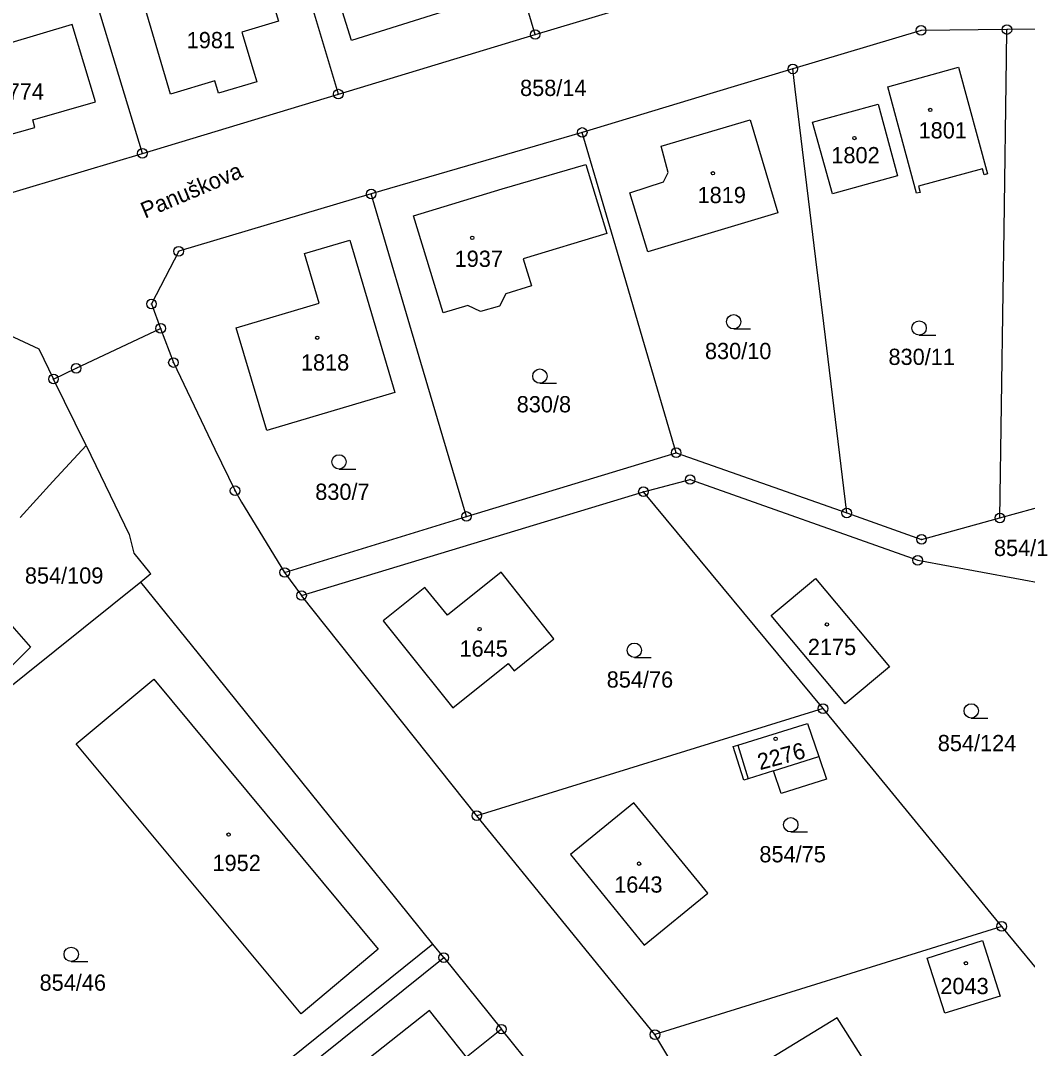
# Model space of a CAD drawing. Extents: x -680203 to -673936, y -1102717 to -1093650.
# Drawn here: x -679106 to -679000.6, y -1097626.7 to -1097519.2 of the extents above; entities that cross this region are included whole.
import ezdxf

# ---------------------------------------------------------------- set-up
doc = ezdxf.new("R2010")
doc.units = 0
for name, color, linetype in [('SOxx02xx_Koleje_param další_Popis10', 7, 'Continuous'), ('SOxx02xx_Staničení_Popis10', 7, 'Continuous'), ('SOxxxxxx_Koleje_hlavní_body_Popis10', 7, 'Continuous'), ('SOxxxxxx_Koleje_param další_Popis10', 7, 'Continuous'), ('SOxxxxxx_Osa_bod_P', 7, 'Continuous'), ('SOxxxxxx_Staničení_Popis10', 7, 'Continuous'), ('x_prac', 7, 'Continuous')]:
    doc.layers.add(name, color=color, linetype=linetype)

msp = doc.modelspace()

# ---------------------------------------------------------------- linework, layer by layer
at = {"layer": 'SOxx02xx_Koleje_param další_Popis10'}
for centre, radius in [((-679052.09, -1097520.62), 0.5), ((-679011.7, -1097520.18), 0.5), ((-679011.7, -1097520.18), 0.0303), ((-679002.71, -1097520.1), 0.5), ((-679002.71, -1097520.1), 0.0303), ((-679052.09, -1097520.62), 0.0303), ((-679025.12, -1097524.22), 0.5), ((-679025.12, -1097524.22), 0.0303), ((-679072.69, -1097526.85), 0.5), ((-679072.69, -1097526.85), 0.0303), ((-679047.16, -1097530.86), 0.5), ((-679047.16, -1097530.86), 0.0303), ((-679093.2, -1097533.05), 0.5), ((-679093.2, -1097533.05), 0.0303), ((-679069.25, -1097537.3), 0.5), ((-679069.25, -1097537.3), 0.0303), ((-679089.4, -1097543.3), 0.5), ((-679089.4, -1097543.3), 0.0303), ((-679092.25, -1097548.81), 0.5), ((-679092.25, -1097548.81), 0.0303), ((-679091.29, -1097551.36), 0.5), ((-679091.29, -1097551.36), 0.0303), ((-679089.95, -1097554.94), 0.5), ((-679100.13, -1097555.54), 0.5), ((-679100.13, -1097555.54), 0.0303), ((-679089.95, -1097554.94), 0.0303), ((-679102.5, -1097556.66), 0.5), ((-679102.5, -1097556.66), 0.0303), ((-679037.33, -1097564.37), 0.5), ((-679037.33, -1097564.37), 0.0303), ((-679035.87, -1097567.18), 0.5), ((-679035.87, -1097567.18), 0.0303), ((-679083.5, -1097568.35), 0.5), ((-679083.5, -1097568.35), 0.0303), ((-679040.76, -1097568.45), 0.5), ((-679040.76, -1097568.45), 0.0303), ((-679059.28, -1097571.04), 0.5), ((-679019.48, -1097570.68), 0.5), ((-679019.48, -1097570.68), 0.0303), ((-679003.45, -1097571.2), 0.5), ((-679059.28, -1097571.04), 0.0303), ((-679003.45, -1097571.2), 0.0303), ((-679011.65, -1097573.44), 0.5), ((-679011.65, -1097573.44), 0.0303), ((-679012.05, -1097575.63), 0.5), ((-679012.05, -1097575.63), 0.0303), ((-679078.31, -1097576.9), 0.5), ((-679078.31, -1097576.9), 0.0303), ((-679076.54, -1097579.31), 0.5), ((-679076.54, -1097579.31), 0.0303), ((-679021.96, -1097591.15), 0.5), ((-679021.96, -1097591.15), 0.0303), ((-679058.2, -1097602.35), 0.5), ((-679058.2, -1097602.35), 0.0303), ((-679003.26, -1097613.93), 0.5), ((-679003.26, -1097613.93), 0.0303), ((-679061.66, -1097617.2), 0.5), ((-679061.66, -1097617.2), 0.0303), ((-679055.62, -1097624.69), 0.5), ((-679055.62, -1097624.69), 0.0303), ((-679039.55, -1097625.26), 0.5), ((-679039.55, -1097625.26), 0.0303)]:
    msp.add_circle(centre, radius, dxfattribs=at)
at = {"layer": 'SOxxxxxx_Koleje_hlavní_body_Popis10'}
for p, q in [((-679031.31, -1097551.42), (-679029.56, -1097551.42)), ((-679011.9, -1097552.08), (-679010.15, -1097552.08)), ((-679051.6, -1097557.11), (-679049.85, -1097557.11)), ((-679072.62, -1097566.08), (-679070.87, -1097566.08)), ((-679041.71, -1097585.79), (-679039.96, -1097585.79)), ((-679006.45, -1097592.13), (-679004.7, -1097592.13)), ((-679025.34, -1097604.05), (-679023.59, -1097604.05)), ((-679100.65, -1097617.6), (-679098.9, -1097617.6))]:
    msp.add_line(p, q, dxfattribs=at)
for centre in [(-679031.31, -1097550.67), (-679011.9, -1097551.33), (-679051.6, -1097556.36), (-679072.62, -1097565.33), (-679041.71, -1097585.04), (-679006.45, -1097591.38), (-679025.34, -1097603.3), (-679100.65, -1097616.85)]:
    msp.add_circle(centre, 0.75, dxfattribs=at)
at = {"layer": 'SOxxxxxx_Koleje_param další_Popis10'}
for centre in [(-679010.74, -1097528.51), (-679018.67, -1097531.45), (-679033.48, -1097535.14), (-679058.67, -1097541.89), (-679074.9, -1097552.35), (-679021.56, -1097582.33), (-679057.9, -1097582.83), (-679026.92, -1097594.31), (-679084.18, -1097604.33), (-679041.21, -1097607.37), (-679007.01, -1097617.79)]:
    msp.add_circle(centre, 0.175, dxfattribs=at)
at = {"layer": 'SOxxxxxx_Staničení_Popis10'}
for p, q in [((-679030.88, -1097594.96), (-679029.78, -1097598.49)), ((-679027.14, -1097597.65), (-679022.41, -1097596.15))]:
    msp.add_line(p, q, dxfattribs=at)
at = {"layer": 'x_prac'}
for p, q in [((-679052.09, -1097520.62), (-679064.54, -1097478.98)), ((-679072.69, -1097526.85), (-679085.11, -1097485.36)), ((-679093.2, -1097533.05), (-679105.63, -1097491.91)), ((-679052.09, -1097520.62), (-679031.47, -1097514.43)), ((-679072.69, -1097526.85), (-679052.09, -1097520.62)), ((-679093.2, -1097533.05), (-679072.69, -1097526.85)), ((-679047.16, -1097530.86), (-679069.25, -1097537.3)), ((-679115.21, -1097539.66), (-679093.2, -1097533.05)), ((-679100.13, -1097555.54), (-679091.29, -1097551.36)), ((-679102.5, -1097556.66), (-679100.13, -1097555.54)), ((-679099.1, -1097563.62), (-679102.5, -1097556.66)), ((-679102.59, -1097567.38), (-679099.1, -1097563.62)), ((-679059.28, -1097571.04), (-679037.33, -1097564.37)), ((-679037.33, -1097564.37), (-679019.48, -1097570.68)), ((-679105.99, -1097571.15), (-679102.59, -1097567.38)), ((-679040.76, -1097568.45), (-679035.87, -1097567.18)), ((-679003.45, -1097571.2), (-678987, -1097566.67)), ((-679076.54, -1097579.31), (-679040.76, -1097568.45)), ((-679021.96, -1097591.15), (-679040.76, -1097568.45)), ((-679078.31, -1097576.9), (-679059.28, -1097571.04)), ((-679078.31, -1097576.9), (-679076.54, -1097579.31)), ((-679093.36, -1097577.91), (-679108.85, -1097590.31)), ((-679058.2, -1097602.35), (-679076.54, -1097579.31)), ((-679021.96, -1097591.15), (-679058.2, -1097602.35)), ((-679003.26, -1097613.93), (-679021.96, -1097591.15)), ((-679039.55, -1097625.26), (-679058.2, -1097602.35)), ((-679003.26, -1097613.93), (-679039.55, -1097625.26)), ((-678984.53, -1097636.69), (-679003.26, -1097613.93)), ((-679062.79, -1097615.8), (-679102.21, -1097647.44)), ((-679061.66, -1097617.2), (-679062.79, -1097615.8)), ((-679101.21, -1097648.88), (-679061.66, -1097617.2)), ((-679061.66, -1097617.2), (-679055.62, -1097624.69)), ((-679055.62, -1097624.69), (-679059.29, -1097627.63)), ((-679051.84, -1097629.37), (-679055.62, -1097624.69))]:
    msp.add_line(p, q, dxfattribs=at)
for points in [[(-679064.7, -1097506.92), (-679062.26, -1097506.15), (-679060.95, -1097510.34), (-679063.38, -1097511.1), (-679061.19, -1097518.07), (-679071.31, -1097521.25), (-679075.76, -1097507.08), (-679065.65, -1097503.9), (-679064.7, -1097506.92)], [(-679085.23, -1097526.75), (-679085.63, -1097525.48), (-679090.25, -1097526.85), (-679093.08, -1097517.28), (-679084.82, -1097514.82), (-679085.1, -1097513.86), (-679080.94, -1097512.61), (-679078.94, -1097519.22), (-679082.78, -1097520.37), (-679081.61, -1097524.3), (-679081.23, -1097525.58), (-679085.23, -1097526.75)], [(-679111.14, -1097532.23), (-679104.45, -1097530.33), (-679104.68, -1097529.54), (-679098.09, -1097527.67), (-679100.56, -1097519.58), (-679113.77, -1097523.5), (-679112.88, -1097526.46), (-679114.14, -1097528.41), (-679112.01, -1097529.36), (-679111.14, -1097532.23)], [(-679002.71, -1097520.1), (-679011.7, -1097520.18), (-679025.12, -1097524.22)], [(-679003.45, -1097571.2), (-679003.1, -1097547.62), (-679003.01, -1097541.04), (-679002.75, -1097523.12), (-679002.71, -1097520.1)], [(-678979.71, -1097520.32), (-678988.1, -1097520), (-678988.8, -1097519.98), (-679002.71, -1097520.1)], [(-679025.12, -1097524.22), (-679033.46, -1097526.73), (-679047.16, -1097530.86)], [(-679019.48, -1097570.68), (-679022.02, -1097549.7), (-679022.56, -1097545.28), (-679024.86, -1097526.35), (-679025.12, -1097524.22)], [(-679004.74, -1097535.2), (-679005.11, -1097535.3), (-679005.28, -1097534.66), (-679011.96, -1097536.47), (-679011.78, -1097537.13), (-679012.16, -1097537.23), (-679015.18, -1097526.08), (-679007.77, -1097524.02), (-679004.74, -1097535.2)], [(-679023.06, -1097529.78), (-679019.49, -1097528.81), (-679016.2, -1097527.91), (-679014.16, -1097535.39), (-679017.43, -1097536.3), (-679020.98, -1097537.28), (-679023.06, -1097529.78)], [(-679038.89, -1097532.3), (-679029.57, -1097529.55), (-679026.7, -1097539.28), (-679040.3, -1097543.34), (-679042.17, -1097537.18), (-679038.65, -1097536.03), (-679038.16, -1097535.05), (-679038.89, -1097532.3)], [(-679037.33, -1097564.37), (-679040.64, -1097553.09), (-679042.78, -1097545.8), (-679047.16, -1097530.86)], [(-679059.12, -1097548.96), (-679061.73, -1097549.73), (-679064.82, -1097539.58), (-679055.55, -1097536.76), (-679046.77, -1097534.23), (-679044.59, -1097541.42), (-679053.33, -1097544.07), (-679052.47, -1097546.9), (-679055.15, -1097547.75), (-679055.81, -1097549.04), (-679057.82, -1097549.61), (-679059.12, -1097548.96)], [(-679069.25, -1097537.3), (-679089.4, -1097543.3), (-679092.25, -1097548.81), (-679091.29, -1097551.36)], [(-679059.28, -1097571.04), (-679061.75, -1097562.7), (-679064.05, -1097554.92), (-679069.25, -1097537.3)], [(-679071.5, -1097542.12), (-679066.77, -1097558.08), (-679080.16, -1097562.04), (-679083.37, -1097551.31), (-679074.68, -1097548.71), (-679076.22, -1097543.53), (-679071.5, -1097542.12)], [(-679132.38, -1097556.26), (-679111.48, -1097550.04), (-679104.04, -1097553.49), (-679102.5, -1097556.66)], [(-679091.29, -1097551.36), (-679089.95, -1097554.94), (-679085.63, -1097563.99), (-679083.5, -1097568.35), (-679082.82, -1097569.54), (-679078.31, -1097576.9)], [(-679099.1, -1097563.62), (-679094.59, -1097572.94), (-679094.09, -1097574.9)], [(-679035.87, -1097567.18), (-679012.05, -1097575.63), (-678998.49, -1097578.13)], [(-679019.48, -1097570.68), (-679011.65, -1097573.44), (-679003.45, -1097571.2)], [(-679094.09, -1097574.9), (-679092.45, -1097576.92), (-679092.33, -1097577.06), (-679093.36, -1097577.91)], [(-679111.55, -1097577.18), (-679104.92, -1097584.73), (-679109.47, -1097589.28), (-679115.94, -1097581.98)], [(-679063.63, -1097578.46), (-679068, -1097581.97), (-679065.64, -1097584.92), (-679060.71, -1097591.08), (-679054.91, -1097586.41), (-679054.28, -1097587.19), (-679050.14, -1097583.85), (-679055.64, -1097576.86), (-679061.25, -1097581.38), (-679063.63, -1097578.46)], [(-679062.79, -1097615.8), (-679067.7, -1097609.72), (-679072.6, -1097603.64), (-679077.51, -1097597.56), (-679082.42, -1097591.48), (-679087.32, -1097585.39), (-679093.36, -1097577.91)], [(-679014.99, -1097586.76), (-679019.65, -1097590.63), (-679027.4, -1097581.4), (-679022.74, -1097577.53), (-679014.99, -1097586.76)], [(-679100.12, -1097594.84), (-679092.01, -1097588.08), (-679068.51, -1097616.31), (-679076.59, -1097623.09), (-679100.12, -1097594.84)], [(-679030.88, -1097594.96), (-679023.57, -1097592.7), (-679022.41, -1097596.15), (-679021.61, -1097598.52), (-679026.34, -1097600.04), (-679027.14, -1097597.65), (-679029.78, -1097598.49), (-679030.26, -1097598.64), (-679031.36, -1097595.11), (-679030.88, -1097594.96)], [(-679041.76, -1097601.02), (-679048.39, -1097606.41), (-679040.69, -1097615.89), (-679034.03, -1097610.47), (-679041.76, -1097601.02)], [(-679011.05, -1097617.27), (-679005.26, -1097615.42), (-679003.43, -1097621.24), (-679009.21, -1097623.02), (-679011.05, -1097617.27)], [(-679059.29, -1097627.63), (-679063.15, -1097622.73), (-679071.19, -1097629.09), (-679073.32, -1097630.76), (-679069.96, -1097635), (-679067.84, -1097633.33), (-679067.28, -1097634.04)], [(-679014.94, -1097632.24), (-679020.47, -1097623.5), (-679031.15, -1097630.03), (-679028.69, -1097633.9), (-679028.18, -1097633.58), (-679024.97, -1097638.57), (-679014.94, -1097632.24)], [(-679025.48, -1097651.06), (-679031.92, -1097637.99), (-679039.55, -1097625.26)]]:
    msp.add_lwpolyline(points, dxfattribs=at)

# ---------------------------------------------------------------- texts
at = {"layer": 'SOxx02xx_Staničení_Popis10'}
msp.add_text('Panuškova', height=1.7, rotation=23, dxfattribs=at).set_placement((-679092.92, -1097539.9))
at = {"layer": 'SOxxxxxx_Osa_bod_P'}
for s, p in [('1981', (-679088.56, -1097522.05)), ('858/14', (-679053.67, -1097527.05)), ('1774', (-679108.56, -1097527.42)), ('1801', (-679011.96, -1097531.49)), ('1802', (-679021.09, -1097534.09)), ('1819', (-679035.09, -1097538.26)), ('1937', (-679060.52, -1097544.93)), ('830/10', (-679034.32, -1097554.58)), ('830/11', (-679015.11, -1097555.19)), ('1818', (-679076.61, -1097555.78)), ('830/8', (-679054.02, -1097560.15)), ('830/7', (-679075.11, -1097569.31)), ('854/1', (-679004.07, -1097575.18)), ('854/109', (-679105.5, -1097578.07)), ('1645', (-679060.01, -1097585.71)), ('2175', (-679023.55, -1097585.54)), ('854/76', (-679044.6, -1097588.95)), ('854/124', (-679009.95, -1097595.6)), ('854/75', (-679028.62, -1097607.23)), ('1952', (-679085.86, -1097608.14)), ('1643', (-679043.82, -1097610.4)), ('854/46', (-679103.96, -1097620.66)), ('2043', (-679009.68, -1097621.02))]:
    msp.add_text(s, height=1.7, dxfattribs=at).set_placement(p)
msp.add_text('2276', height=1.7, rotation=15, dxfattribs=at).set_placement((-679028.56, -1097597.59))

doc.saveas('drawing.dxf')
